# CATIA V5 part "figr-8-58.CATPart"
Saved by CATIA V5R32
Part number: Part1
Bounding box of the stored display mesh (mm): x -50.499 to 50.499, y -68.48 to 68.48, z -46 to 50
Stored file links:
  D:\PROJECTS\Project 2022\CATIA V5 6R 2022\Resources\Part Files\c08_catia_v5_6r2022_prt\figr-8-58.CATPart
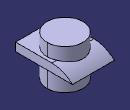
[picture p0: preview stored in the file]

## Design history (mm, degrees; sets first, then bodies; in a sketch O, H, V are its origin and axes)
Body1 (main body)
  Sketch1 on xy-plane, origin (0, 0, 0), H (1, 0, 0), V (0, 1, 0)
    line L1 (-50.499, 68.4797) -> (50.499, 68.4797)
    line L2 (50.499, 68.4797) -> (50.499, -68.4797)
    line L3 (50.499, -68.4797) -> (-50.499, -68.4797)
    line L4 (-50.499, -68.4797) -> (-50.499, 68.4797)
    axis line L5 (50.499, -68.4797) -> (-50.499, 68.4797)
    horizontal: L1 H, L3 H
    vertical: L2 V, L4 V
    midpoint: O L5
  Pad1: profile Sketch1, direction (0, 0, 1), length 20
  Fillet1: radius 71, on edge [face of Pad1 | face of Pad1]
  Body2
    Sketch2 on xy-plane, origin (0, 0, 0), H (1, 0, 0), V (0, 1, 0)
      circle A1 centre (0, 0) radius 43.2524
      point P1 (0, 43.2524)
      coincidence: A1 P1, P1 V
    Pad2: profile Sketch2, direction (0, 0, 1), length 50, opposite side length 46
  Assemble1: tool Body2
